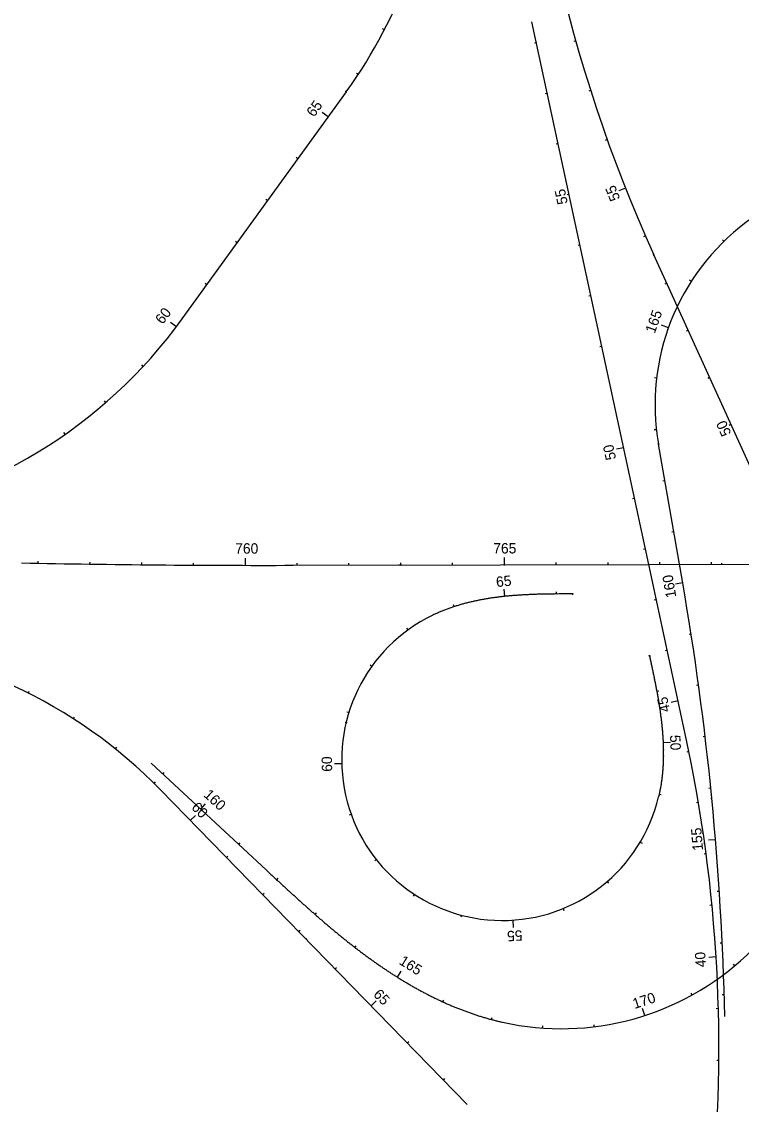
# Model space of a CAD drawing. Extents: x 448091 to 665917, y 1461380 to 1587607.
# Drawn here: x 555631 to 557020, y 1495926 to 1498016 of the extents above; entities that cross this region are included whole.
import ezdxf

# ---------------------------------------------------------------- set-up
doc = ezdxf.new("R2010")
doc.units = 0
doc.layers.add('TextShtNo', color=7, linetype='Continuous')
doc.layers.add('TextTitle', color=7, linetype='Continuous')

msp = doc.modelspace()

# ---------------------------------------------------------------- linework, layer by layer
at = {"layer": 'TextShtNo'}
for p, q in [((556841.6, 1496968.5), (556616.1, 1498016.1)), ((555941, 1497442.4), (556257.8, 1497880.9)), ((557122.6, 1496969.2), (556851.4, 1497565.8)), ((556906.5, 1496935.9), (556860.2, 1497200.8)), ((556155.4, 1496966.7), (556555.4, 1496967.7)), ((556555.4, 1496967.7), (556841.6, 1496968.5)), ((556841.6, 1496968.5), (557122.6, 1496969.2)), ((556912.7, 1496638), (556841.6, 1496968.5)), ((555880.9, 1496584.5), (556102.8, 1496378.7)), ((555899.1, 1496533.2), (556490.8, 1495926.1))]:
    msp.add_line(p, q, dxfattribs=at)
for centre, radius, start, end in [((559459.4, 1498751.1), 2864.7, 180.15, 204.4403), ((555483.7, 1498440.1), 954.9, 324.1545, 356.3397), ((557294.4, 1497276.6), 440.7, 64.1669, 189.9105), ((555166.9, 1498001.6), 954.9, 278.4009, 324.1545), ((556096.5, 1519883.8), 22917.2, 268.83609, 270.14719), ((551429.4, 1495978.9), 5560, 1.2018, 9.9105), ((556558.8, 1496591), 310, 115.5683, 346.7376), ((555215.3, 1495866.7), 954.9, 44.2633, 86.1473), ((556673.1, 1496593), 520.9, 257.4087, 9.314), ((554112.2, 1496035.2), 2864.7, 336.1403, 12.1472)]:
    msp.add_arc(centre, radius, start, end, dxfattribs=at)
for points in [[(556694.6, 1496911.4), (556690.8, 1496911.4), (556687.1, 1496911.4), (556683.4, 1496911.4), (556679.7, 1496911.4), (556676, 1496911.4), (556672.3, 1496911.4), (556668.5, 1496911.3), (556664.8, 1496911.3), (556661.1, 1496911.3), (556657.4, 1496911.2), (556653.7, 1496911.2), (556650, 1496911.1), (556646.2, 1496911.1), (556642.5, 1496911), (556638.8, 1496910.9), (556635.1, 1496910.9), (556631.4, 1496910.8), (556627.7, 1496910.7), (556624, 1496910.6), (556620.2, 1496910.4), (556616.5, 1496910.3), (556612.8, 1496910.1), (556609.1, 1496910), (556605.4, 1496909.8), (556601.7, 1496909.6), (556598, 1496909.4), (556594.3, 1496909.2), (556590.6, 1496909), (556586.8, 1496908.7), (556583.1, 1496908.4), (556579.4, 1496908.1), (556575.7, 1496907.8), (556572, 1496907.5), (556568.3, 1496907.2), (556564.6, 1496906.8), (556560.9, 1496906.4), (556557.2, 1496906), (556553.6, 1496905.6), (556549.9, 1496905.1), (556546.2, 1496904.6), (556542.5, 1496904.1), (556538.8, 1496903.6), (556535.1, 1496903), (556531.5, 1496902.5), (556527.8, 1496901.9), (556524.1, 1496901.2), (556520.5, 1496900.6), (556516.8, 1496899.9), (556513.2, 1496899.2), (556509.5, 1496898.4), (556505.9, 1496897.7), (556502.3, 1496896.9), (556498.7, 1496896), (556495, 1496895.2), (556491.4, 1496894.3), (556487.8, 1496893.3), (556484.2, 1496892.4), (556480.7, 1496891.4), (556477.1, 1496890.4), (556473.5, 1496889.3), (556470, 1496888.2), (556466.4, 1496887.1), (556462.9, 1496885.9), (556459.4, 1496884.7), (556455.9, 1496883.5), (556452.4, 1496882.2), (556448.9, 1496880.9), (556445.5, 1496879.5), (556442, 1496878.1), (556438.6, 1496876.7), (556435.2, 1496875.2), (556431.8, 1496873.7), (556428.4, 1496872.2), (556425, 1496870.6)], [(556843, 1496791.9), (556843.8, 1496788.3), (556844.6, 1496784.6), (556845.3, 1496781), (556846.1, 1496777.4), (556846.9, 1496773.7), (556847.7, 1496770.1), (556848.4, 1496766.5), (556849.2, 1496762.8), (556850, 1496759.2), (556850.7, 1496755.5), (556851.5, 1496751.9), (556852.2, 1496748.3), (556852.9, 1496744.6), (556853.7, 1496741), (556854.4, 1496737.3), (556855.1, 1496733.7), (556855.8, 1496730), (556856.5, 1496726.4), (556857.2, 1496722.7), (556857.8, 1496719.1), (556858.5, 1496715.4), (556859.2, 1496711.8), (556859.8, 1496708.1), (556860.4, 1496704.4), (556861, 1496700.8), (556861.6, 1496697.1), (556862.2, 1496693.4), (556862.7, 1496689.7), (556863.3, 1496686.1), (556863.8, 1496682.4), (556864.3, 1496678.7), (556864.8, 1496675), (556865.3, 1496671.3), (556865.7, 1496667.7), (556866.1, 1496664), (556866.5, 1496660.3), (556866.9, 1496656.6), (556867.3, 1496652.9), (556867.6, 1496649.2), (556868, 1496645.5), (556868.2, 1496641.8), (556868.5, 1496638.1), (556868.8, 1496634.3), (556869, 1496630.6), (556869.2, 1496626.9), (556869.3, 1496623.2), (556869.5, 1496619.5), (556869.6, 1496615.8), (556869.7, 1496612.1), (556869.7, 1496608.4), (556869.7, 1496604.6), (556869.7, 1496600.9), (556869.7, 1496597.2), (556869.6, 1496593.5), (556869.5, 1496589.8), (556869.4, 1496586.1), (556869.2, 1496582.4), (556869, 1496578.6), (556868.7, 1496574.9), (556868.5, 1496571.2), (556868.2, 1496567.5), (556867.8, 1496563.8), (556867.4, 1496560.1), (556867, 1496556.4), (556866.5, 1496552.7), (556866, 1496549.1), (556865.5, 1496545.4), (556864.9, 1496541.7), (556864.3, 1496538.1), (556863.6, 1496534.4), (556862.9, 1496530.8), (556862.2, 1496527.1), (556861.4, 1496523.5), (556860.6, 1496519.9)], [(556102.8, 1496378.7), (556108.3, 1496373.7), (556113.7, 1496368.6), (556119.2, 1496363.6), (556124.6, 1496358.5), (556130.1, 1496353.5), (556135.5, 1496348.5), (556141, 1496343.4), (556146.5, 1496338.4), (556152, 1496333.4), (556157.5, 1496328.4), (556163, 1496323.4), (556168.5, 1496318.4), (556174, 1496313.4), (556179.5, 1496308.5), (556185.1, 1496303.5), (556190.7, 1496298.6), (556196.2, 1496293.7), (556201.8, 1496288.8), (556207.5, 1496283.9), (556213.1, 1496279.1), (556218.7, 1496274.2), (556224.4, 1496269.4), (556230.1, 1496264.7), (556235.8, 1496259.9), (556241.5, 1496255.2), (556247.3, 1496250.5), (556253.1, 1496245.8), (556258.9, 1496241.2), (556264.7, 1496236.5), (556270.6, 1496232), (556276.4, 1496227.4), (556282.3, 1496222.9), (556288.3, 1496218.4), (556294.2, 1496214), (556300.2, 1496209.6), (556306.3, 1496205.2), (556312.3, 1496200.9), (556318.4, 1496196.7), (556324.5, 1496192.4), (556330.7, 1496188.3), (556336.8, 1496184.1), (556343, 1496180), (556349.3, 1496176), (556355.6, 1496172), (556361.9, 1496168.1), (556368.2, 1496164.2), (556374.6, 1496160.4), (556381, 1496156.7), (556387.4, 1496153), (556393.9, 1496149.3), (556400.4, 1496145.7), (556407, 1496142.2), (556413.6, 1496138.8), (556420.2, 1496135.4), (556426.9, 1496132.1), (556433.5, 1496128.9), (556440.3, 1496125.7), (556447, 1496122.6), (556453.8, 1496119.6), (556460.7, 1496116.6), (556467.5, 1496113.8), (556474.4, 1496111), (556481.3, 1496108.3), (556488.3, 1496105.7), (556495.3, 1496103.2), (556502.3, 1496100.7), (556509.4, 1496098.4), (556516.4, 1496096.1), (556523.5, 1496094), (556530.7, 1496091.9), (556537.9, 1496089.9), (556545, 1496088.1), (556552.3, 1496086.3), (556559.5, 1496084.6)]]:
    msp.add_spline(points, degree=3, dxfattribs=at)
at = {"layer": 'TextTitle'}
for p, q in [((556331.3, 1498000.2), (556327.7, 1498002)), ((556624.8, 1497975.7), (556620.9, 1497974.9)), ((556700.8, 1497978.9), (556696.9, 1497977.8)), ((556280.6, 1497914), (556277.3, 1497916.2)), ((556257.9, 1497881.1), (556256.3, 1497882.2)), ((556645.8, 1497878), (556641.9, 1497877.1)), ((556729.4, 1497883.1), (556725.6, 1497881.8)), ((556222.8, 1497832.4), (556211.4, 1497840.6)), ((556761.4, 1497788.3), (556757.6, 1497787)), ((556666.9, 1497780.2), (556663, 1497779.4)), ((556164.2, 1497751.4), (556161, 1497753.7)), ((556687.9, 1497682.4), (556684, 1497681.6)), ((556796.6, 1497694.7), (556783.6, 1497689.6)), ((556105.6, 1497670.3), (556102.4, 1497672.7)), ((556835.1, 1497602.4), (556831.4, 1497600.8)), ((556047.1, 1497589.3), (556043.8, 1497591.6)), ((556708.9, 1497584.7), (556705, 1497583.8)), ((556986.6, 1497592.1), (556983.8, 1497595)), ((556851.4, 1497565.9), (556849.6, 1497565.1)), ((556923.5, 1497514.8), (556920.2, 1497517)), ((555988.5, 1497508.2), (555985.3, 1497510.5)), ((556876.2, 1497511.3), (556872.6, 1497509.6)), ((556730, 1497486.9), (556726.1, 1497486.1)), ((555929.8, 1497427.3), (555918.6, 1497435.7)), ((556877.7, 1497420.2), (556884.8, 1497439.3)), ((556879.5, 1497425.3), (556866.3, 1497430)), ((556917.6, 1497420.2), (556913.9, 1497418.6)), ((556751, 1497389.2), (556747.1, 1497388.3)), ((555865.6, 1497350.7), (555862.7, 1497353.4)), ((556856.6, 1497328.2), (556852.7, 1497328.6)), ((556959, 1497329.2), (556955.3, 1497327.5)), ((555793.7, 1497281.2), (555791.1, 1497284.2)), ((555715, 1497219.6), (555712.7, 1497222.9)), ((556856.3, 1497228.4), (556852.3, 1497227.9)), ((557000.3, 1497238.2), (556996.7, 1497236.5)), ((556860.2, 1497201.6), (556860.2, 1497199.9)), ((556793.1, 1497193.6), (556779.4, 1497190.7)), ((556861.1, 1497200.8), (556859.3, 1497200.8)), ((556872.6, 1497129.7), (556868.7, 1497129)), ((556814.2, 1497095.9), (556810.3, 1497095)), ((556889.8, 1497031.2), (556885.9, 1497030.5)), ((556835.2, 1496998.1), (556831.3, 1496997.3)), ((555662.9, 1496970.7), (555663, 1496974.7)), ((555762.9, 1496969), (555763, 1496973)), ((555862.9, 1496967.8), (555862.9, 1496971.8)), ((556062.9, 1496966.6), (556062.9, 1496980.6)), ((556562.9, 1496967.7), (556562.8, 1496981.7)), ((556662.9, 1496968), (556662.9, 1496972)), ((556762.9, 1496968.3), (556762.9, 1496972.3)), ((556862.9, 1496968.5), (556862.9, 1496972.5)), ((556962.9, 1496968.8), (556962.9, 1496972.8)), ((555962.9, 1496967), (555962.9, 1496971)), ((556162.9, 1496966.7), (556162.9, 1496970.7)), ((556262.9, 1496967), (556262.9, 1496971)), ((556362.9, 1496967.2), (556358.9, 1496967.2)), ((556362.9, 1496967.2), (556362.9, 1496971.2)), ((556462.9, 1496967.5), (556462.9, 1496971.5)), ((556982.9, 1496968.8), (556982.9, 1496970.8)), ((556907, 1496932.7), (556893.2, 1496930.3)), ((556563.8, 1496906.7), (556562.3, 1496920.6)), ((556663.6, 1496911.3), (556663.6, 1496915.3)), ((556465.9, 1496886.9), (556464.7, 1496890.7)), ((556856.2, 1496900.4), (556852.3, 1496899.5)), ((556377, 1496842.1), (556374.7, 1496845.3)), ((556923.3, 1496834.1), (556919.3, 1496833.4)), ((556877.3, 1496802.6), (556873.4, 1496801.8)), ((556306.8, 1496771.5), (556303.5, 1496773.8)), ((555644, 1496720), (555645.8, 1496723.6)), ((556857, 1496723.5), (556861, 1496724.2)), ((556937.8, 1496735.1), (556933.8, 1496734.6)), ((556898.3, 1496704.8), (556884.6, 1496701.9)), ((556262.6, 1496682.3), (556258.7, 1496683.4)), ((555730.8, 1496670.5), (555733, 1496673.9)), ((556257.3, 1496663), (556255.4, 1496663.4)), ((556869.3, 1496624.4), (556883.3, 1496625)), ((556950.5, 1496635.9), (556946.5, 1496635.5)), ((555812, 1496612.2), (555814.5, 1496615.4)), ((556919.2, 1496607), (556915.3, 1496606.2)), ((556248.9, 1496583.6), (556234.9, 1496583.3)), ((555903.3, 1496563.7), (555906, 1496566.7)), ((555886.7, 1496545.8), (555889.5, 1496548.6)), ((556961.4, 1496536.5), (556957.4, 1496536.1)), ((556861.7, 1496524.9), (556865.6, 1496524.1)), ((556963.4, 1496516.6), (556961.4, 1496516.4)), ((555976.6, 1496495.7), (555986.2, 1496506)), ((556937.4, 1496508.7), (556933.5, 1496508.1)), ((555956.6, 1496474.3), (555966.6, 1496484)), ((556267.2, 1496485.8), (556263.5, 1496484.4)), ((556940.7, 1496489), (556938.7, 1496488.7)), ((556943.8, 1496469.2), (556941.8, 1496468.9)), ((556946.7, 1496449.4), (556944.8, 1496449.2)), ((556050, 1496427.7), (556052.7, 1496430.7)), ((556825.1, 1496432.3), (556828.6, 1496430.3)), ((556949.6, 1496429.6), (556947.6, 1496429.4)), ((556970.5, 1496436.9), (556956.6, 1496435.8)), ((556952.3, 1496409.8), (556948.3, 1496409.3)), ((556026.4, 1496402.7), (556029.2, 1496405.5)), ((556315.6, 1496398.8), (556312.5, 1496396.3)), ((556123.3, 1496359.7), (556126, 1496362.7)), ((556761.1, 1496356.1), (556763.7, 1496353)), ((556096.2, 1496331.1), (556099, 1496333.8)), ((556389.1, 1496331.6), (556386.9, 1496328.2)), ((556977.9, 1496337.2), (556973.9, 1496337)), ((556676.2, 1496304.1), (556677.7, 1496300.4)), ((556963.6, 1496310.5), (556959.6, 1496310.1)), ((556197.4, 1496292.6), (556200.1, 1496295.7)), ((556480.1, 1496291.1), (556479.1, 1496287.3)), ((556166, 1496259.4), (556168.8, 1496262.2)), ((556579.2, 1496281.6), (556580.1, 1496267.7)), ((556179.9, 1496245.1), (556181.4, 1496246.5)), ((556274.5, 1496228.9), (556276.9, 1496232.1)), ((556983.4, 1496237.4), (556979.4, 1496237.2)), ((556971.5, 1496210.8), (556957.5, 1496209.9)), ((556235.8, 1496187.8), (556238.6, 1496190.6)), ((556356.3, 1496171.5), (556363.8, 1496183.4)), ((557007.7, 1496193.8), (557005.2, 1496196.9)), ((556925.4, 1496137.3), (556923.5, 1496140.8)), ((556987.2, 1496137.4), (556983.2, 1496137.3)), ((556305.6, 1496116.2), (556315.6, 1496126)), ((556444.2, 1496123.9), (556445.8, 1496127.5)), ((556833.9, 1496097.5), (556829.5, 1496110.9)), ((556975.9, 1496110.9), (556971.9, 1496110.8)), ((556538.1, 1496089.9), (556539.1, 1496093.7)), ((556636.6, 1496073.4), (556636.8, 1496077.4)), ((556736.4, 1496076), (556735.9, 1496079.9)), ((556375.4, 1496044.6), (556378.2, 1496047.4)), ((556976.8, 1496010.9), (556972.8, 1496010.9)), ((556445.1, 1495973), (556448, 1495975.8))]:
    msp.add_line(p, q, dxfattribs=at)
for centre in [(556860.2, 1497200.8), (556362.9, 1496967.2), (556562.9, 1496967.7), (556694.6, 1496911.4), (556843, 1496791.9), (556257.3, 1496663)]:
    msp.add_circle(centre, 0.8, dxfattribs=at)

# ---------------------------------------------------------------- texts
for s, rotation, p in [('65', 54.1545, (556195.4, 1497830.6)), ('55', 102.1472, (556685.4, 1497665.6)), ('55', 111.6383, (556786.7, 1497674.5)), ('60', 53.0259, (555903.2, 1497430.6)), ('165', 70.283, (556853, 1497413)), ('50', 114.4403, (557001.4, 1497221.3)), ('50', 102.1472, (556778.7, 1497172.2)), ('760', 359.9159, (556043.2, 1496989.3)), ('765', 0.1533, (556541.4, 1496989.5)), ('65', 5.9161, (556547.8, 1496924.5)), ('160', 99.8777, (556894.9, 1496905.7)), ('45', 102.1472, (556883.1, 1496685.3)), ('50', 272.461, (556882.5, 1496638.8)), ('60', 91.3543, (556230.6, 1496568.3)), ('160', 317.1587, (555980.9, 1496521.9)), ('60', 314.2633, (555957.4, 1496498)), ('155', 94.7252, (556946.5, 1496416.5)), ('55', 183.7668, (556597.1, 1496262.5)), ('40', 93.5141, (556952.2, 1496191.3)), ('165', 327.9133, (556358.1, 1496198)), ('65', 314.2633, (556308.6, 1496137)), ('170', 17.9823, (556814.2, 1496110.1))]:
    msp.add_text(s, height=20, rotation=rotation, dxfattribs=at).set_placement(p)

doc.saveas('drawing.dxf')
